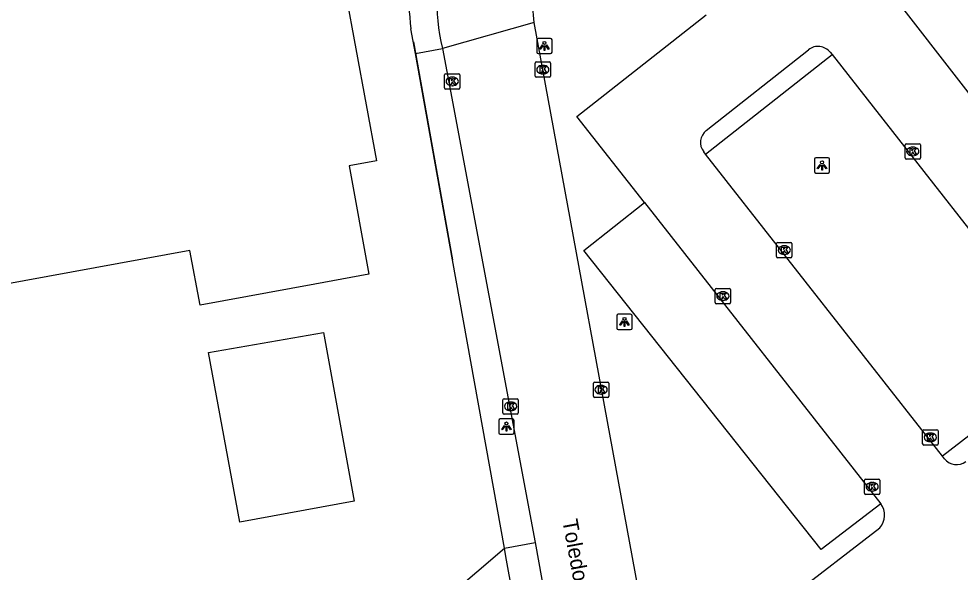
# Model space of a CAD drawing. Extents: x 159451 to 160663, y 388402 to 389723.
# Drawn here: x 159640.5 to 159701.9, y 388928.2 to 388964.3 of the extents above; entities that cross this region are included whole.
import ezdxf

# ---------------------------------------------------------------- set-up
doc = ezdxf.new("R2010")
doc.units = 0
for name, color, linetype in [('IMGEO_Kolk', 7, 'Continuous'), ('IMGEO_Lichtpunt', 7, 'Continuous'), ('IMGEO_Muur', 7, 'Continuous'), ('IMGEO_Openbare_ruimte_label', 7, 'Continuous'), ('IMGEO_Pand', 7, 'Continuous'), ('IMGEO_Parkeervlak_open', 7, 'Continuous'), ('IMGEO_Rijbaan_lokaal_open', 7, 'Continuous'), ('IMGEO_Voetpad_open', 7, 'Continuous')]:
    doc.layers.add(name, color=color, linetype=linetype)

msp = doc.modelspace()

# ---------------------------------------------------------------- linework, layer by layer
at = {"layer": 'IMGEO_Kolk'}
for p, q in [((159674.19, 388960.595), (159674.19, 388961.447)), ((159674.265, 388961.521), (159675.117, 388961.521)), ((159675.191, 388961.447), (159675.191, 388960.595)), ((159674.678, 388961.301), (159674.703, 388961.301)), ((159668.285, 388959.824), (159668.285, 388960.676)), ((159668.36, 388960.75), (159669.212, 388960.75)), ((159668.773, 388960.53), (159668.798, 388960.53)), ((159669.286, 388960.676), (159669.286, 388959.824)), ((159675.117, 388960.521), (159674.265, 388960.521)), ((159674.701, 388960.741), (159674.676, 388960.741)), ((159669.212, 388959.75), (159668.36, 388959.75)), ((159668.796, 388959.97), (159668.771, 388959.97)), ((159698.312, 388955.257), (159698.312, 388956.109)), ((159698.387, 388956.183), (159699.239, 388956.183)), ((159698.8, 388955.963), (159698.825, 388955.963)), ((159699.313, 388956.109), (159699.313, 388955.257)), ((159698.823, 388955.403), (159698.798, 388955.403)), ((159699.239, 388955.183), (159698.387, 388955.183)), ((159689.935, 388948.82), (159689.935, 388949.672)), ((159690.01, 388949.746), (159690.862, 388949.746)), ((159690.423, 388949.526), (159690.448, 388949.526)), ((159690.936, 388949.672), (159690.936, 388948.82)), ((159690.862, 388948.746), (159690.01, 388948.746)), ((159690.446, 388948.966), (159690.421, 388948.966)), ((159686.009, 388946.748), (159686.861, 388946.748)), ((159685.934, 388945.822), (159685.934, 388946.674)), ((159686.422, 388946.528), (159686.447, 388946.528)), ((159686.935, 388946.674), (159686.935, 388945.822)), ((159686.861, 388945.748), (159686.009, 388945.748)), ((159686.445, 388945.968), (159686.42, 388945.968)), ((159677.992, 388939.712), (159677.992, 388940.564)), ((159678.067, 388940.638), (159678.919, 388940.638)), ((159678.993, 388940.564), (159678.993, 388939.712)), ((159678.48, 388940.418), (159678.505, 388940.418)), ((159672.092, 388938.627), (159672.092, 388939.479)), ((159672.167, 388939.553), (159673.019, 388939.553)), ((159672.58, 388939.333), (159672.605, 388939.333)), ((159673.093, 388939.479), (159673.093, 388938.627)), ((159678.919, 388939.638), (159678.067, 388939.638)), ((159678.503, 388939.858), (159678.478, 388939.858)), ((159672.603, 388938.773), (159672.578, 388938.773)), ((159673.019, 388938.553), (159672.167, 388938.553)), ((159699.533, 388937.531), (159700.385, 388937.531)), ((159699.458, 388936.605), (159699.458, 388937.457)), ((159699.946, 388937.311), (159699.971, 388937.311)), ((159700.459, 388937.457), (159700.459, 388936.605)), ((159700.385, 388936.531), (159699.533, 388936.531)), ((159699.969, 388936.751), (159699.944, 388936.751)), ((159695.666, 388933.38), (159695.666, 388934.232)), ((159695.741, 388934.306), (159696.593, 388934.306)), ((159696.154, 388934.086), (159696.179, 388934.086)), ((159696.667, 388934.232), (159696.667, 388933.38)), ((159696.593, 388933.306), (159695.741, 388933.306)), ((159696.177, 388933.526), (159696.152, 388933.526))]:
    msp.add_line(p, q, dxfattribs=at)
for points in [[(159674.19, 388960.595), (159674.19, 388961.447)], [(159674.265, 388961.521), (159675.117, 388961.521)], [(159675.191, 388961.447), (159675.191, 388960.595)], [(159674.511, 388961.221), (159674.634, 388961.221), (159674.634, 388961.07), (159674.764, 388961.221), (159674.928, 388961.221), (159674.782, 388961.07), (159674.935, 388960.821), (159674.783, 388960.821), (159674.698, 388960.985), (159674.634, 388960.918), (159674.634, 388960.821), (159674.511, 388960.821), (159674.511, 388961.221)], [(159668.285, 388959.824), (159668.285, 388960.676)], [(159668.36, 388960.75), (159669.212, 388960.75)], [(159668.606, 388960.45), (159668.729, 388960.45), (159668.729, 388960.299), (159668.859, 388960.45), (159669.023, 388960.45), (159668.877, 388960.299), (159669.03, 388960.05), (159668.878, 388960.05), (159668.793, 388960.214), (159668.729, 388960.147), (159668.729, 388960.05), (159668.606, 388960.05), (159668.606, 388960.45)], [(159669.286, 388960.676), (159669.286, 388959.824)], [(159675.117, 388960.521), (159674.265, 388960.521)], [(159669.212, 388959.75), (159668.36, 388959.75)], [(159698.312, 388955.257), (159698.312, 388956.109)], [(159698.387, 388956.183), (159699.239, 388956.183)], [(159699.313, 388956.109), (159699.313, 388955.257)], [(159698.633, 388955.883), (159698.756, 388955.883), (159698.756, 388955.732), (159698.886, 388955.883), (159699.05, 388955.883), (159698.904, 388955.732), (159699.057, 388955.483), (159698.905, 388955.483), (159698.82, 388955.647), (159698.756, 388955.58), (159698.756, 388955.483), (159698.633, 388955.483), (159698.633, 388955.883)], [(159699.239, 388955.183), (159698.387, 388955.183)], [(159689.935, 388948.82), (159689.935, 388949.672)], [(159690.01, 388949.746), (159690.862, 388949.746)], [(159690.256, 388949.446), (159690.379, 388949.446), (159690.379, 388949.295), (159690.509, 388949.446), (159690.673, 388949.446), (159690.527, 388949.295), (159690.68, 388949.046), (159690.528, 388949.046), (159690.443, 388949.21), (159690.379, 388949.143), (159690.379, 388949.046), (159690.256, 388949.046), (159690.256, 388949.446)], [(159690.936, 388949.672), (159690.936, 388948.82)], [(159690.862, 388948.746), (159690.01, 388948.746)], [(159686.009, 388946.748), (159686.861, 388946.748)], [(159685.934, 388945.822), (159685.934, 388946.674)], [(159686.255, 388946.448), (159686.378, 388946.448), (159686.378, 388946.297), (159686.508, 388946.448), (159686.672, 388946.448), (159686.526, 388946.297), (159686.679, 388946.048), (159686.527, 388946.048), (159686.442, 388946.212), (159686.378, 388946.145), (159686.378, 388946.048), (159686.255, 388946.048), (159686.255, 388946.448)], [(159686.935, 388946.674), (159686.935, 388945.822)], [(159686.861, 388945.748), (159686.009, 388945.748)], [(159677.992, 388939.712), (159677.992, 388940.564)], [(159678.067, 388940.638), (159678.919, 388940.638)], [(159678.993, 388940.564), (159678.993, 388939.712)], [(159678.313, 388940.338), (159678.436, 388940.338), (159678.436, 388940.187), (159678.566, 388940.338), (159678.73, 388940.338), (159678.584, 388940.187), (159678.737, 388939.938), (159678.585, 388939.938), (159678.5, 388940.102), (159678.436, 388940.035), (159678.436, 388939.938), (159678.313, 388939.938), (159678.313, 388940.338)], [(159672.092, 388938.627), (159672.092, 388939.479)], [(159672.167, 388939.553), (159673.019, 388939.553)], [(159673.093, 388939.479), (159673.093, 388938.627)], [(159678.919, 388939.638), (159678.067, 388939.638)], [(159672.413, 388939.253), (159672.536, 388939.253), (159672.536, 388939.102), (159672.666, 388939.253), (159672.83, 388939.253), (159672.684, 388939.102), (159672.837, 388938.853), (159672.685, 388938.853), (159672.6, 388939.017), (159672.536, 388938.95), (159672.536, 388938.853), (159672.413, 388938.853), (159672.413, 388939.253)], [(159673.019, 388938.553), (159672.167, 388938.553)], [(159699.533, 388937.531), (159700.385, 388937.531)], [(159699.458, 388936.605), (159699.458, 388937.457)], [(159699.779, 388937.231), (159699.902, 388937.231), (159699.902, 388937.08), (159700.032, 388937.231), (159700.196, 388937.231), (159700.05, 388937.08), (159700.203, 388936.831), (159700.051, 388936.831), (159699.966, 388936.995), (159699.902, 388936.928), (159699.902, 388936.831), (159699.779, 388936.831), (159699.779, 388937.231)], [(159700.459, 388937.457), (159700.459, 388936.605)], [(159700.385, 388936.531), (159699.533, 388936.531)], [(159695.666, 388933.38), (159695.666, 388934.232)], [(159695.741, 388934.306), (159696.593, 388934.306)], [(159695.987, 388934.006), (159696.11, 388934.006), (159696.11, 388933.855), (159696.24, 388934.006), (159696.404, 388934.006), (159696.258, 388933.855), (159696.411, 388933.606), (159696.259, 388933.606), (159696.174, 388933.77), (159696.11, 388933.703), (159696.11, 388933.606), (159695.987, 388933.606), (159695.987, 388934.006)], [(159696.667, 388934.232), (159696.667, 388933.38)], [(159696.593, 388933.306), (159695.741, 388933.306)]]:
    msp.add_lwpolyline(points, dxfattribs=at)
for centre, start, end in [((159674.267, 388961.445), 91.55205, 178.44795), ((159674.267, 388961.445), 91.55205, 178.44795), ((159675.115, 388961.445), 1.55205, 88.44795), ((159675.115, 388961.445), 1.55205, 88.44795), ((159668.362, 388960.674), 91.55205, 178.44795), ((159668.362, 388960.674), 91.55205, 178.44795), ((159669.21, 388960.674), 1.55205, 88.44795), ((159669.21, 388960.674), 1.55205, 88.44795), ((159674.267, 388960.597), 181.55205, 268.44795), ((159674.267, 388960.597), 181.55205, 268.44795), ((159675.115, 388960.597), 271.55205, 358.44795), ((159675.115, 388960.597), 271.55205, 358.44795), ((159668.362, 388959.826), 181.55205, 268.44795), ((159668.362, 388959.826), 181.55205, 268.44795), ((159669.21, 388959.826), 271.55205, 358.44795), ((159669.21, 388959.826), 271.55205, 358.44795), ((159698.389, 388956.107), 91.55205, 178.44795), ((159698.389, 388956.107), 91.55205, 178.44795), ((159699.237, 388956.107), 1.55205, 88.44795), ((159699.237, 388956.107), 1.55205, 88.44795), ((159698.389, 388955.259), 181.55205, 268.44795), ((159698.389, 388955.259), 181.55205, 268.44795), ((159699.237, 388955.259), 271.55205, 358.44795), ((159699.237, 388955.259), 271.55205, 358.44795), ((159690.012, 388949.67), 91.55205, 178.44795), ((159690.012, 388949.67), 91.55205, 178.44795), ((159690.86, 388949.67), 1.55205, 88.44795), ((159690.86, 388949.67), 1.55205, 88.44795), ((159690.012, 388948.822), 181.55205, 268.44795), ((159690.012, 388948.822), 181.55205, 268.44795), ((159690.86, 388948.822), 271.55205, 358.44795), ((159690.86, 388948.822), 271.55205, 358.44795), ((159686.011, 388946.672), 91.55205, 178.44795), ((159686.011, 388946.672), 91.55205, 178.44795), ((159686.859, 388946.672), 1.55205, 88.44795), ((159686.859, 388946.672), 1.55205, 88.44795), ((159686.011, 388945.824), 181.55205, 268.44795), ((159686.011, 388945.824), 181.55205, 268.44795), ((159686.859, 388945.824), 271.55205, 358.44795), ((159686.859, 388945.824), 271.55205, 358.44795), ((159678.069, 388940.562), 91.55205, 178.44795), ((159678.069, 388940.562), 91.55205, 178.44795), ((159678.917, 388940.562), 1.55205, 88.44795), ((159678.917, 388940.562), 1.55205, 88.44795), ((159672.169, 388939.477), 91.55205, 178.44795), ((159672.169, 388939.477), 91.55205, 178.44795), ((159673.017, 388939.477), 1.55205, 88.44795), ((159673.017, 388939.477), 1.55205, 88.44795), ((159678.069, 388939.714), 181.55205, 268.44795), ((159678.069, 388939.714), 181.55205, 268.44795), ((159678.917, 388939.714), 271.55205, 358.44795), ((159678.917, 388939.714), 271.55205, 358.44795), ((159672.169, 388938.629), 181.55205, 268.44795), ((159672.169, 388938.629), 181.55205, 268.44795), ((159673.017, 388938.629), 271.55205, 358.44795), ((159673.017, 388938.629), 271.55205, 358.44795), ((159699.535, 388937.455), 91.55205, 178.44795), ((159699.535, 388937.455), 91.55205, 178.44795), ((159700.383, 388937.455), 1.55205, 88.44795), ((159700.383, 388937.455), 1.55205, 88.44795), ((159699.535, 388936.607), 181.55205, 268.44795), ((159699.535, 388936.607), 181.55205, 268.44795), ((159700.383, 388936.607), 271.55205, 358.44795), ((159700.383, 388936.607), 271.55205, 358.44795), ((159695.743, 388934.23), 91.55205, 178.44795), ((159695.743, 388934.23), 91.55205, 178.44795), ((159696.591, 388934.23), 1.55205, 88.44795), ((159696.591, 388934.23), 1.55205, 88.44795), ((159695.743, 388933.382), 181.55205, 268.44795), ((159695.743, 388933.382), 181.55205, 268.44795), ((159696.591, 388933.382), 271.55205, 358.44795), ((159696.591, 388933.382), 271.55205, 358.44795)]:
    msp.add_arc(centre, 0.0765, start, end, dxfattribs=at)
for centre, major_axis, ratio, start_param, end_param in [((159674.677, 388961.021), (-0.387, 0.002), 0.722429, 4.712389, 7.853982), ((159674.702, 388961.021), (-0.39, 0.002), 0.717154, 1.570796, 4.712389), ((159668.772, 388960.25), (-0.387, 0.002), 0.722429, 4.712389, 7.853982), ((159668.797, 388960.25), (-0.39, 0.002), 0.717154, 1.570796, 4.712389), ((159698.799, 388955.683), (-0.387, 0.002), 0.722429, 4.712389, 7.853982), ((159698.824, 388955.683), (-0.39, 0.002), 0.717154, 1.570796, 4.712389), ((159690.422, 388949.246), (-0.387, 0.002), 0.722429, 4.712389, 7.853982), ((159690.447, 388949.246), (-0.39, 0.002), 0.717154, 1.570796, 4.712389), ((159686.421, 388946.248), (-0.387, 0.002), 0.722429, 4.712389, 7.853982), ((159686.446, 388946.248), (-0.39, 0.002), 0.717154, 1.570796, 4.712389), ((159678.479, 388940.138), (-0.387, 0.002), 0.722429, 4.712389, 7.853982), ((159678.504, 388940.138), (-0.39, 0.002), 0.717154, 1.570796, 4.712389), ((159672.579, 388939.053), (-0.387, 0.002), 0.722429, 4.712389, 7.853982), ((159672.604, 388939.053), (-0.39, 0.002), 0.717154, 1.570796, 4.712389), ((159699.945, 388937.031), (-0.387, 0.002), 0.722429, 4.712389, 7.853982), ((159699.97, 388937.031), (-0.39, 0.002), 0.717154, 1.570796, 4.712389), ((159696.153, 388933.806), (-0.387, 0.002), 0.722429, 4.712389, 7.853982), ((159696.178, 388933.806), (-0.39, 0.002), 0.717154, 1.570796, 4.712389)]:
    msp.add_ellipse(centre, major_axis=major_axis, ratio=ratio, start_param=start_param, end_param=end_param, dxfattribs=at)
at = {"layer": 'IMGEO_Lichtpunt'}
for p, q in [((159674.298, 388962.967), (159674.298, 388962.16)), ((159674.298, 388962.967), (159674.298, 388962.16)), ((159675.2, 388963.062), (159674.392, 388963.062)), ((159675.2, 388963.062), (159674.392, 388963.062)), ((159675.294, 388962.16), (159675.294, 388962.967)), ((159675.294, 388962.16), (159675.294, 388962.967)), ((159674.392, 388962.066), (159675.2, 388962.066)), ((159674.392, 388962.066), (159675.2, 388962.066)), ((159692.398, 388955.176), (159692.398, 388954.369)), ((159692.398, 388955.176), (159692.398, 388954.369)), ((159693.3, 388955.271), (159692.492, 388955.271)), ((159693.3, 388955.271), (159692.492, 388955.271)), ((159693.394, 388954.369), (159693.394, 388955.176)), ((159693.394, 388954.369), (159693.394, 388955.176)), ((159692.492, 388954.275), (159693.3, 388954.275)), ((159692.492, 388954.275), (159693.3, 388954.275)), ((159679.516, 388944.962), (159679.516, 388944.155)), ((159679.516, 388944.962), (159679.516, 388944.155)), ((159680.418, 388945.057), (159679.61, 388945.057)), ((159680.418, 388945.057), (159679.61, 388945.057)), ((159680.512, 388944.155), (159680.512, 388944.962)), ((159680.512, 388944.155), (159680.512, 388944.962)), ((159679.61, 388944.061), (159680.418, 388944.061)), ((159679.61, 388944.061), (159680.418, 388944.061)), ((159671.82, 388938.138), (159671.82, 388937.331)), ((159671.82, 388938.138), (159671.82, 388937.331)), ((159672.722, 388938.233), (159671.914, 388938.233)), ((159672.722, 388938.233), (159671.914, 388938.233)), ((159672.816, 388937.331), (159672.816, 388938.138)), ((159672.816, 388937.331), (159672.816, 388938.138)), ((159671.914, 388937.237), (159672.722, 388937.237)), ((159671.914, 388937.237), (159672.722, 388937.237))]:
    msp.add_line(p, q, dxfattribs=at)
for points in [[(159674.672, 388962.631), (159674.711, 388962.603), (159674.523, 388962.341), (159674.485, 388962.368), (159674.672, 388962.631)], [(159674.774, 388962.583), (159674.821, 388962.583), (159674.821, 388962.261), (159674.774, 388962.261), (159674.774, 388962.583)], [(159674.884, 388962.603), (159674.922, 388962.63), (159675.109, 388962.368), (159675.07, 388962.34), (159674.884, 388962.603)], [(159692.772, 388954.84), (159692.811, 388954.812), (159692.623, 388954.55), (159692.585, 388954.577), (159692.772, 388954.84)], [(159692.874, 388954.792), (159692.921, 388954.792), (159692.921, 388954.47), (159692.874, 388954.47), (159692.874, 388954.792)], [(159692.984, 388954.812), (159693.022, 388954.839), (159693.209, 388954.577), (159693.17, 388954.549), (159692.984, 388954.812)], [(159679.89, 388944.626), (159679.929, 388944.598), (159679.741, 388944.336), (159679.703, 388944.363), (159679.89, 388944.626)], [(159679.992, 388944.578), (159680.039, 388944.578), (159680.039, 388944.256), (159679.992, 388944.256), (159679.992, 388944.578)], [(159680.102, 388944.598), (159680.14, 388944.625), (159680.327, 388944.363), (159680.288, 388944.335), (159680.102, 388944.598)], [(159672.194, 388937.802), (159672.233, 388937.774), (159672.045, 388937.512), (159672.007, 388937.539), (159672.194, 388937.802)], [(159672.296, 388937.754), (159672.343, 388937.754), (159672.343, 388937.432), (159672.296, 388937.432), (159672.296, 388937.754)], [(159672.406, 388937.774), (159672.444, 388937.801), (159672.631, 388937.539), (159672.592, 388937.511), (159672.406, 388937.774)]]:
    msp.add_lwpolyline(points, dxfattribs=at)
for centre in [(159674.797, 388962.765), (159692.897, 388954.974), (159680.015, 388944.76), (159672.319, 388937.936)]:
    msp.add_circle(centre, 0.0994, dxfattribs=at)
for centre, start, end in [((159674.392, 388962.967), 90, 180), ((159674.392, 388962.967), 90, 180), ((159675.2, 388962.967), 0, 90), ((159675.2, 388962.967), 0, 90), ((159674.392, 388962.16), 180, 270), ((159674.392, 388962.16), 180, 270), ((159675.2, 388962.16), 270, 0), ((159675.2, 388962.16), 270, 360), ((159692.492, 388955.176), 90, 180), ((159692.492, 388955.176), 90, 180), ((159693.3, 388955.176), 0, 90), ((159693.3, 388955.176), 0, 90), ((159692.492, 388954.369), 180, 270), ((159692.492, 388954.369), 180, 270), ((159693.3, 388954.369), 270, 0), ((159693.3, 388954.369), 270, 360), ((159679.61, 388944.962), 90, 180), ((159679.61, 388944.962), 90, 180), ((159680.418, 388944.962), 0, 90), ((159680.418, 388944.962), 0, 90), ((159679.61, 388944.155), 180, 270), ((159679.61, 388944.155), 180, 270), ((159680.418, 388944.155), 270, 0), ((159680.418, 388944.155), 270, 360), ((159671.914, 388938.138), 90, 180), ((159671.914, 388938.138), 90, 180), ((159672.722, 388938.138), 0, 90), ((159672.722, 388938.138), 0, 90), ((159671.914, 388937.331), 180, 270), ((159671.914, 388937.331), 180, 270), ((159672.722, 388937.331), 270, 0), ((159672.722, 388937.331), 270, 360)]:
    msp.add_arc(centre, 0.0946, start, end, dxfattribs=at)
at = {"layer": 'IMGEO_Muur'}
msp.add_lwpolyline([(159666.256, 388962.836), (159668.807, 388948.609)], dxfattribs=at)
at = {"layer": 'IMGEO_Pand'}
for points in [[(159658.567, 388965.49), (159661.814, 388966.062), (159663.838, 388955.065), (159662.061, 388954.736), (159663.353, 388947.682), (159659.823, 388947.031), (159652.347, 388945.664), (159651.669, 388949.218), (159616.15, 388942.714), (159615.828, 388944.494), (159595.068, 388940.701), (159596.419, 388933.227), (159609.158, 388924.47), (159610.511, 388924.73), (159611.502, 388919.548), (159611.62, 388919.57), (159611.805, 388918.556)], [(159652.896, 388942.557), (159660.394, 388943.862), (159662.396, 388932.857), (159654.924, 388931.504), (159652.896, 388942.557)]]:
    msp.add_lwpolyline(points, dxfattribs=at)
at = {"layer": 'IMGEO_Parkeervlak_open'}
for points in [[(159685.307, 388955.495), (159693.55, 388961.999)], [(159696.731, 388932.701), (159692.847, 388929.716), (159677.354, 388949.22), (159681.326, 388952.353)], [(159709.063, 388942.213), (159700.749, 388935.8)]]:
    msp.add_lwpolyline(points, dxfattribs=at)
at = {"layer": 'IMGEO_Rijbaan_lokaal_open'}
for points in [[(159720.186, 388944.913), (159716.209, 388941.803), (159693.567, 388970.994)], [(159674.135, 388964.086), (159674.026, 388965.31), (159674.011, 388966.473)], [(159681.326, 388952.353), (159676.913, 388957.959), (159685.35, 388964.585)], [(159674.135, 388964.086), (159668.152, 388962.408)], [(159681.485, 388924.154), (159681.28, 388925.163), (159674.135, 388964.086)], [(159668.152, 388962.408), (159674.192, 388930.162)], [(159685.349, 388957.057), (159692.022, 388962.322)], [(159693.429, 388962.154), (159693.55, 388961.999)], [(159693.55, 388961.999), (159709.063, 388942.213)], [(159685.307, 388955.495), (159685.182, 388955.655)], [(159700.749, 388935.8), (159685.307, 388955.495)], [(159681.326, 388952.353), (159696.731, 388932.701)], [(159700.878, 388935.636), (159700.749, 388935.8)], [(159681.485, 388924.154), (159681.757, 388923.679), (159682.943, 388922.674), (159684.703, 388921.908), (159696.655, 388931.126)], [(159674.192, 388930.162), (159675.645, 388922.073), (159676.123, 388919.495)]]:
    msp.add_lwpolyline(points, dxfattribs=at)
for centre, radius, start, end in [((159680.09, 388965.407), 12.309, 127.59265, 194.10128), ((159692.642, 388961.536), 1.001, 38.11342, 128.26848), ((159685.969, 388956.272), 1, 128.31927, 218.0951), ((159701.665, 388936.253), 1, 218.10766, 307.61202), ((159695.752, 388931.959), 1.229, 317.31978, 37.15501)]:
    msp.add_arc(centre, radius, start, end, dxfattribs=at)
at = {"layer": 'IMGEO_Voetpad_open'}
for points in [[(159666.381, 388962.068), (159666.09, 388963.685)], [(159666.381, 388962.068), (159668.152, 388962.408)], [(159672.185, 388929.801), (159668.807, 388948.609), (159666.381, 388962.068)], [(159672.185, 388929.801), (159674.192, 388930.162)], [(159611.805, 388918.556), (159649.975, 388924.443), (159659.557, 388918.986), (159672.185, 388929.801)], [(159672.732, 388926.753), (159672.283, 388929.255), (159672.185, 388929.801)]]:
    msp.add_lwpolyline(points, dxfattribs=at)
msp.add_arc((159679.967, 388965.547), 14.001, 138.88823, 187.64111, dxfattribs=at)

# ---------------------------------------------------------------- texts
at = {"layer": 'IMGEO_Openbare_ruimte_label'}
msp.add_text('Toledolaan', height=1, rotation=280.48939, dxfattribs=at).set_placement((159675.957, 388931.598))

doc.saveas('drawing.dxf')
